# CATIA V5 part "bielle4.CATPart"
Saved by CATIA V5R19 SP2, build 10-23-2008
Part number: bielle4
Bounding box of the stored display mesh (mm): x 0 to 10, y -70 to 10, z -10 to 10
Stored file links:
  C:\Users\Guillaume\Desktop\ETUDES\IFMA\S3\IAO\Projet IAO\ggaubert_1504\bielle4.CATPart
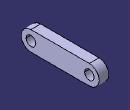
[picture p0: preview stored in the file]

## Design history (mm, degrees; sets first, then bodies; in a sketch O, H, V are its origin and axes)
Parameters
  entraxe_bielle_4 = 60 mm
  largeur_bielle = 20 mm
Body1 (main body)
  Sketch1 on yz-plane, origin (0, 0, 0), H (0, 1, 0), V (0, 0, 1)
    line L1 (-60, 10) -> (0, 10)
    arc A1 centre (0, 0) radius 10 from (0, 10) to (0, -10) cw
    point P3 (0, 0)
    line L2 (0, -10) -> (-60, -10)
    arc A2 centre (-60, 0) radius 10 from (-60, -10) to (-60, 10) cw
    point P6 (-60, 0)
    distance L2 L1 = 20 {= largeur_bielle}
    distance P6 P3 = 60 {= entraxe_bielle_4}
    horizontal: L1 H
    tangency: A1 L1, L2 A1, A2 L1, A2 L2
    coincidence: P3 O
  Sketch2 on yz-plane, origin (0, 0, 0), H (0, 1, 0), V (0, 0, 1)
    circle A1 centre (0, 0) radius 5
    point P1 (0, 0)
    circle A2 centre (-60, 0) radius 5
    point P2 (-60, 0)
    distance P1 P2 = 60 {= entraxe_bielle_4}
    radius A1 = 5
    radius A2 = 5
    coincidence: P1 O, P2 H
  Pad1: profile Sketch1, direction (1, 0, 0), length 10
  Pocket1: profile Sketch2, direction (-1, 0, 0), up to end face of Pad1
